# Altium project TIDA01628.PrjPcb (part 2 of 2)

## Sheet TIDA01628_Signal.SchDoc
size 431 x 279 mm; Date: Not shown in title block; ApprovedBy: Not shown in title block; CheckedBy: Not shown in title block; Author: Not shown in title block; CompanyName: Not shown in title block; Engineer: Not shown in title block; Organization: Not shown in title block; Address1: Not shown in title block; Address2: Not shown in title block; Address3: Not shown in title block; Address4: Not shown in title block; DocumentNumber: 1; Revision: Use project parameter SCH_Rev; SheetNumber: 4; SheetTotal: 5; PageSetup: Record=PageOptions¦CenterHorizontal=True¦CenterVertical=True¦PrintScale=1.00¦XCorrection=1.00¦YCorrection=1.00¦PrintKind=0¦BorderSize=5000000¦LeftOffset=0¦BottomOffset=0¦Orientation=2¦PaperLength=1000¦PaperWidth=1000¦Scale=100¦PaperSource=15¦PrintQuality=600¦MediaType=1¦DitherType=10¦PaperKind=Letter¦PrintScaleMode=1
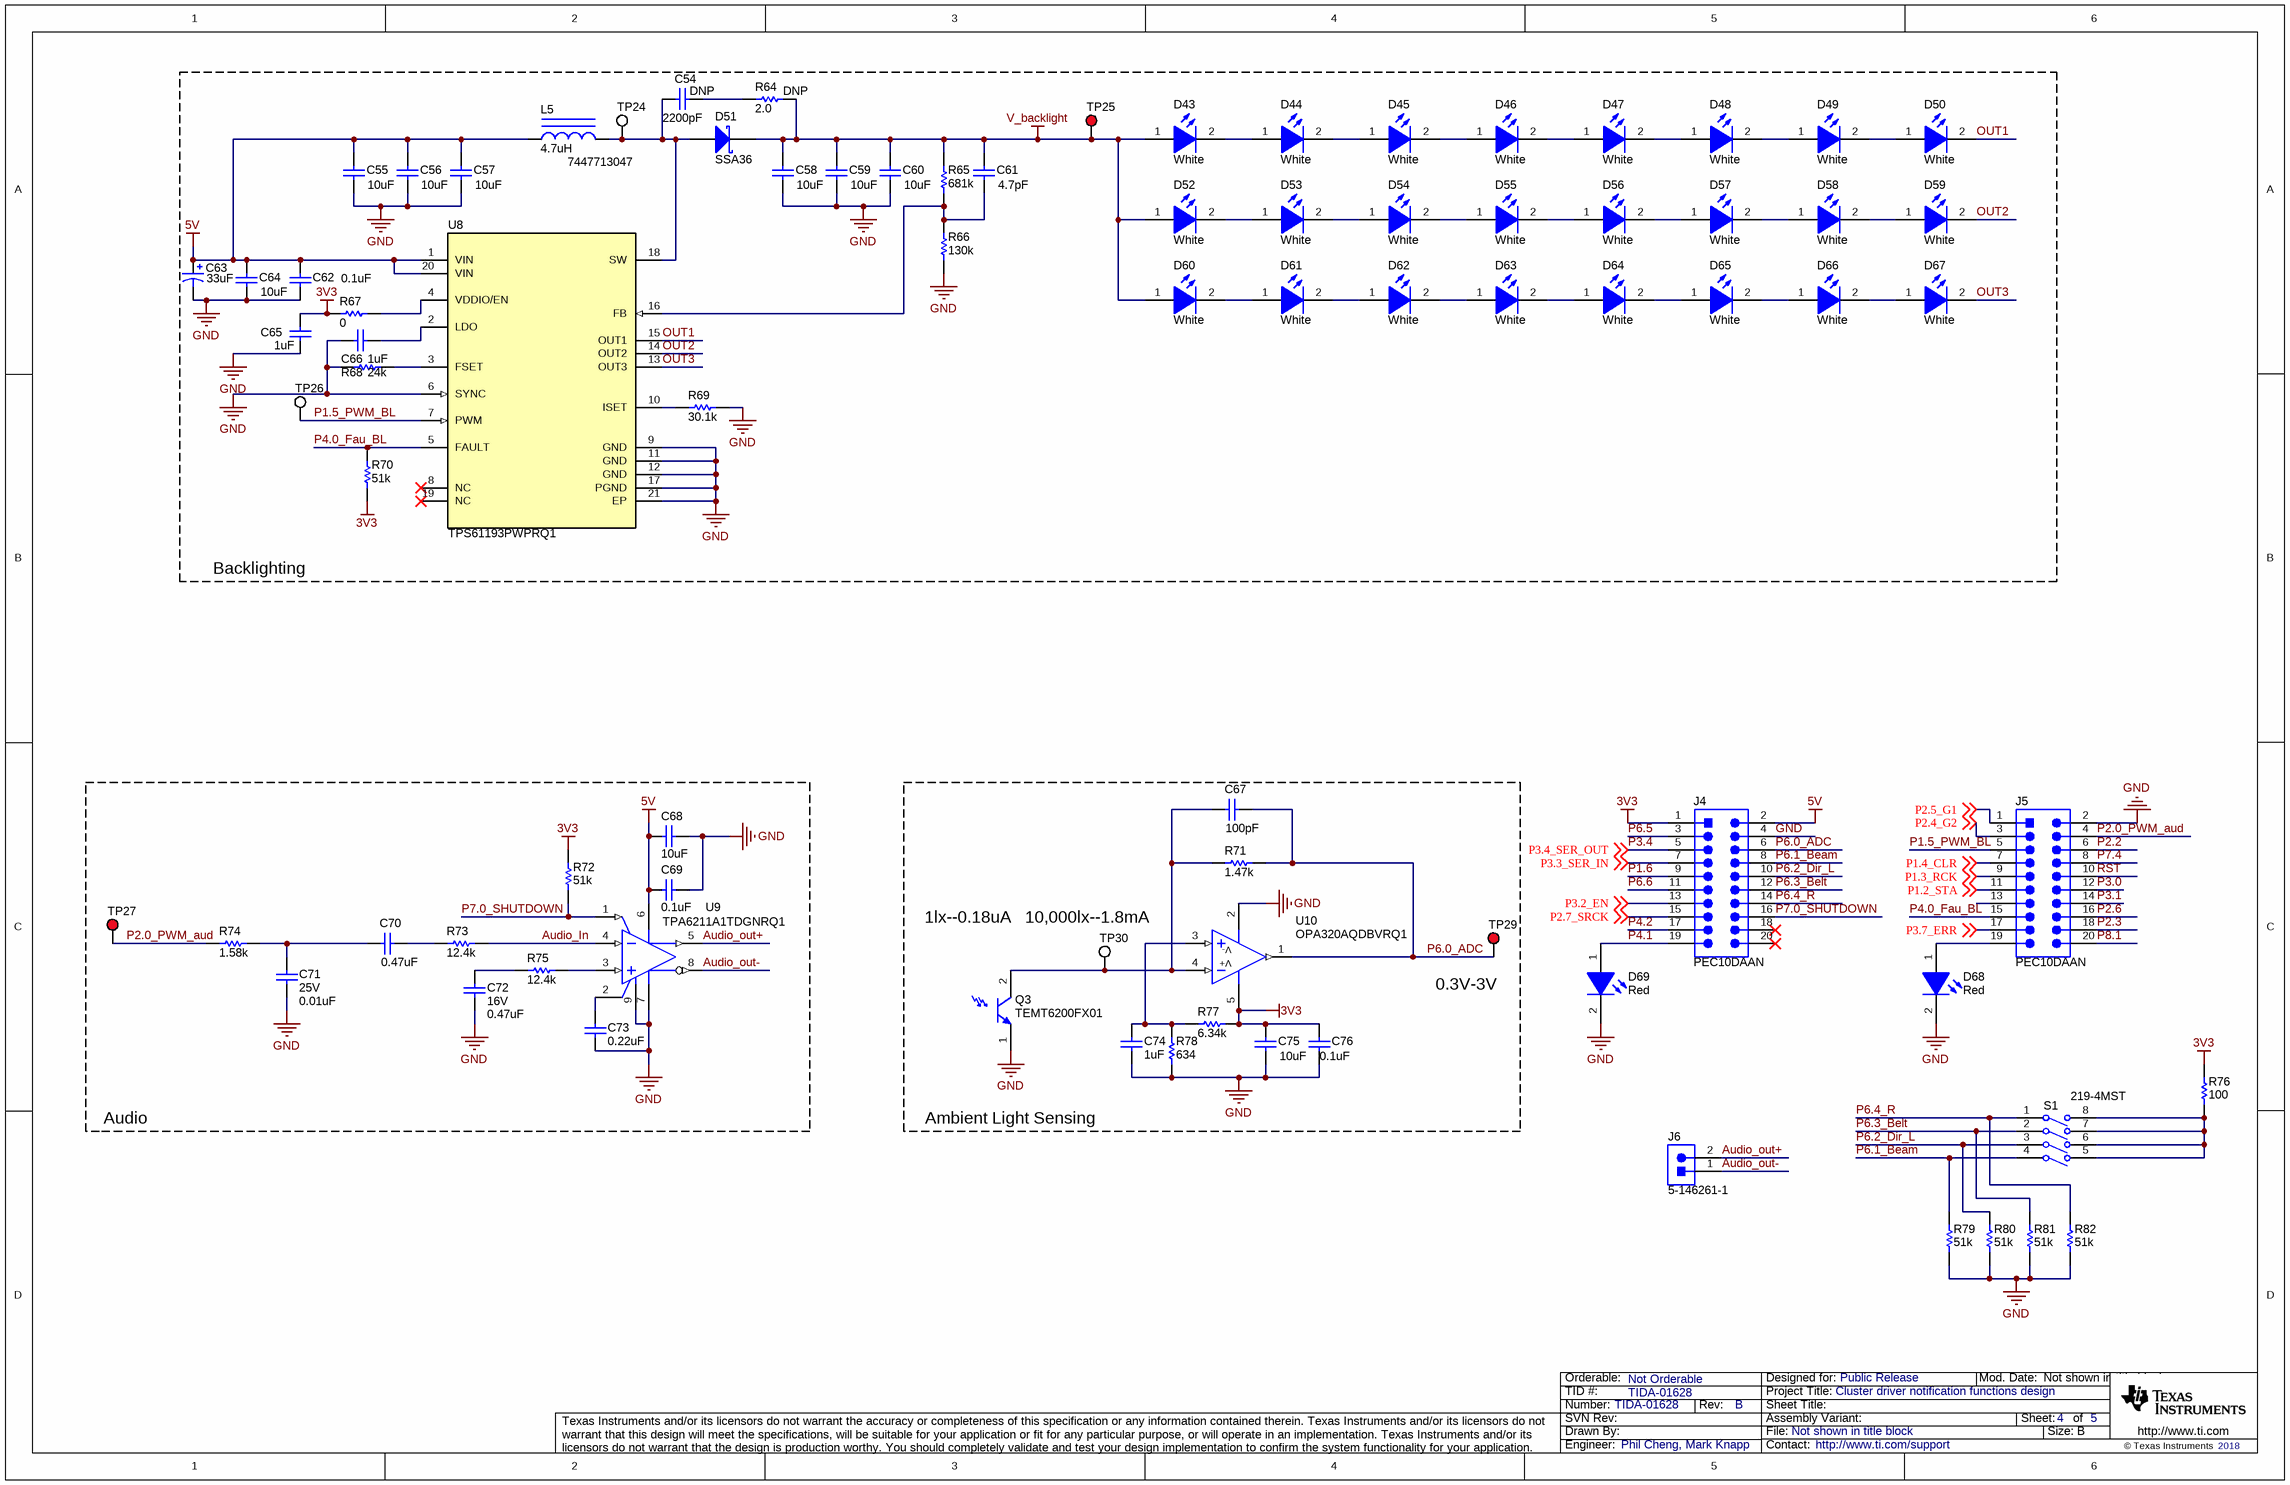
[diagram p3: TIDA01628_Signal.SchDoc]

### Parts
C54  DNP  ValueDisplayed: 2200pF  [0402]
C55  ValueDisplayed: 10uF  [1210_280]  (hidden comment: UMK325AB7106KMHT)
C56  ValueDisplayed: 10uF  [1210_280]  (hidden comment: UMK325AB7106KMHT)
C57  ValueDisplayed: 10uF  [1210_280]  (hidden comment: UMK325AB7106KMHT)
C58  ValueDisplayed: 10uF  [1210_280]  (hidden comment: UMK325AB7106KMHT)
C59  ValueDisplayed: 10uF  [1210_280]  (hidden comment: UMK325AB7106KMHT)
C60  ValueDisplayed: 10uF  [1210_280]  (hidden comment: UMK325AB7106KMHT)
C61  ValueDisplayed: 4.7pF  [0603]  (hidden comment: 06035A4R7CAT2A)
C62  ValueDisplayed: 0.1uF  [0402]  (hidden comment: GCM155R71H104KE02D)
C63  ValueDisplayed: 33uF  [SM_RADIAL_D]  (hidden comment: EEE-FK1V330P)
C64  ValueDisplayed: 10uF  [1210_280]  (hidden comment: UMK325AB7106KMHT)
C65  ValueDisplayed: 1uF  [0603]  (hidden comment: GCM188R71C105KA64D)
C66  ValueDisplayed: 1uF  [0603]  (hidden comment: GCM188R71C105KA64D)
C67  ValueDisplayed: 100pF  [0603]  (hidden comment: C1608C0G1H101J080AE)
C68  ValueDisplayed: 10uF  [1210_280]  (hidden comment: UMK325AB7106KMHT)
C69  ValueDisplayed: 0.1uF  [0402]  (hidden comment: GCM155R71H104KE02D)
C70  ValueDisplayed: 0.47uF  [0603]  (hidden comment: GCM188R71C474KA55D)
C71  VDC_V: 25V  ValueDisplayed: 0.01uF  [0402]  (hidden comment: GCM155R71E103KA37D)
C72  VDC_V: 16V  ValueDisplayed: 0.47uF  [0603]  (hidden comment: GCM188R71C474KA55D)
C73  ValueDisplayed: 0.22uF  [0603]  (hidden comment: CGA3E3X7R1H224K080AB)
C74  ValueDisplayed: 1uF  [0603]  (hidden comment: GCM188R71C105KA64D)
C75  ValueDisplayed: 10uF  [1210_280]  (hidden comment: UMK325AB7106KMHT)
C76  ValueDisplayed: 0.1uF  [0402]  (hidden comment: GCM155R71H104KE02D)
D43  value White  [KW_DPLS32_EC_White]  (hidden comment: KW DPLS32.EC-6H6J-4F8G-1)
D44  value White  [KW_DPLS32_EC_White]  (hidden comment: KW DPLS32.EC-6H6J-4F8G-1)
D45  value White  [KW_DPLS32_EC_White]  (hidden comment: KW DPLS32.EC-6H6J-4F8G-1)
D46  value White  [KW_DPLS32_EC_White]  (hidden comment: KW DPLS32.EC-6H6J-4F8G-1)
D47  value White  [KW_DPLS32_EC_White]  (hidden comment: KW DPLS32.EC-6H6J-4F8G-1)
D48  value White  [KW_DPLS32_EC_White]  (hidden comment: KW DPLS32.EC-6H6J-4F8G-1)
D49  value White  [KW_DPLS32_EC_White]  (hidden comment: KW DPLS32.EC-6H6J-4F8G-1)
D50  value White  [KW_DPLS32_EC_White]  (hidden comment: KW DPLS32.EC-6H6J-4F8G-1)
D51  SSA36  [SMA]
D52  value White  [KW_DPLS32_EC_White]  (hidden comment: KW DPLS32.EC-6H6J-4F8G-1)
D53  value White  [KW_DPLS32_EC_White]  (hidden comment: KW DPLS32.EC-6H6J-4F8G-1)
D54  value White  [KW_DPLS32_EC_White]  (hidden comment: KW DPLS32.EC-6H6J-4F8G-1)
D55  value White  [KW_DPLS32_EC_White]  (hidden comment: KW DPLS32.EC-6H6J-4F8G-1)
D56  value White  [KW_DPLS32_EC_White]  (hidden comment: KW DPLS32.EC-6H6J-4F8G-1)
D57  value White  [KW_DPLS32_EC_White]  (hidden comment: KW DPLS32.EC-6H6J-4F8G-1)
D58  value White  [KW_DPLS32_EC_White]  (hidden comment: KW DPLS32.EC-6H6J-4F8G-1)
D59  value White  [KW_DPLS32_EC_White]  (hidden comment: KW DPLS32.EC-6H6J-4F8G-1)
D60  value White  [KW_DPLS32_EC_White]  (hidden comment: KW DPLS32.EC-6H6J-4F8G-1)
D61  value White  [KW_DPLS32_EC_White]  (hidden comment: KW DPLS32.EC-6H6J-4F8G-1)
D62  value White  [KW_DPLS32_EC_White]  (hidden comment: KW DPLS32.EC-6H6J-4F8G-1)
D63  value White  [KW_DPLS32_EC_White]  (hidden comment: KW DPLS32.EC-6H6J-4F8G-1)
D64  value White  [KW_DPLS32_EC_White]  (hidden comment: KW DPLS32.EC-6H6J-4F8G-1)
D65  value White  [KW_DPLS32_EC_White]  (hidden comment: KW DPLS32.EC-6H6J-4F8G-1)
D66  value White  [KW_DPLS32_EC_White]  (hidden comment: KW DPLS32.EC-6H6J-4F8G-1)
D67  value White  [KW_DPLS32_EC_White]  (hidden comment: KW DPLS32.EC-6H6J-4F8G-1)
D68  value Red  [LED_LTST-C170_Red]  (hidden comment: LTST-C170KRKT)
D69  value Red  [LED_LTST-C170_Red]  (hidden comment: LTST-C170KRKT)
J4  PEC10DAAN  [SULLINS_PEC10DAAN]
J5  PEC10DAAN  [SULLINS_PEC10DAAN]
J6  5-146261-1  [CONN_5-146261-1]
L5  7447713047  ValueDisplayed: 4.7uH  [WE-PD_1030]
Q3  TEMT6200FX01  [VISHAY_TEMT6200FX01]
R64  DNP  ValueDisplayed: 2.0  [2010]
R65  ValueDisplayed: 681k  [0402]  (hidden comment: CRCW0402681KFKED)
R66  ValueDisplayed: 130k  [0402]  (hidden comment: CRCW0402130KFKED)
R67  ValueDisplayed: 0  [0402]  (hidden comment: CRCW04020000Z0ED)
R68  ValueDisplayed: 24k  [0402]  (hidden comment: CRCW040224K0JNED)
R69  ValueDisplayed: 30.1k  [0603]  (hidden comment: CRCW060330K1FKEA)
R70  ValueDisplayed: 51k  [0402]  (hidden comment: CRCW040251K0JNED)
R71  ValueDisplayed: 1.47k  [0603]  (hidden comment: CRCW06031K47FKEA)
R72  ValueDisplayed: 51k  [0402]  (hidden comment: CRCW040251K0JNED)
R73  ValueDisplayed: 12.4k  [0402]  (hidden comment: CRCW040212K4FKED)
R74  ValueDisplayed: 1.58k  [0402]  (hidden comment: CRCW04021K58FKED)
R75  ValueDisplayed: 12.4k  [0402]  (hidden comment: CRCW040212K4FKED)
R76  ValueDisplayed: 100  [0603]  (hidden comment: ERJ-3EKF1000V)
R77  ValueDisplayed: 6.34k  [0603]  (hidden comment: CRCW06036K34FKEA)
R78  ValueDisplayed: 634  [0603]  (hidden comment: CRCW0603634RFKEA)
R79  ValueDisplayed: 51k  [0402]  (hidden comment: CRCW040251K0JNED)
R80  ValueDisplayed: 51k  [0402]  (hidden comment: CRCW040251K0JNED)
R81  ValueDisplayed: 51k  [0402]  (hidden comment: CRCW040251K0JNED)
R82  ValueDisplayed: 51k  [0402]  (hidden comment: CRCW040251K0JNED)
S1  219-4MST  [SW_219-4MST]
TP24  5002  [Keystone5002]  (value not drawn)
TP25  5000  [Keystone5000]  (value not drawn)
TP26  5002  [Keystone5002]  (value not drawn)
TP27  5000  [Keystone5000]  (value not drawn)
TP29  5000  [Keystone5000]  (value not drawn)
TP30  5002  [Keystone5002]  (value not drawn)
U8  TPS61193PWPRQ1  [PWP0020D_M]
U9  TPA6211A1TDGNRQ1  [DGN0008D_L]
U10  OPA320AQDBVRQ1  [DBV0005A_N]

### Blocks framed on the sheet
Backlighting: C54-C66 D43-D67 L5 R64-R70 TP24-TP26 U8
Audio: C68-C73 R72-R75 TP27 U9

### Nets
3V3: C65.1 C75.1 C76.1 J4.1 R67.2 R70.1 R72.2 R76.2 R77.2 U10.5(V+)
5V: C55.1 C56.1 C57.1 C62.1 C63.1(+) C64.1 C68.1 C69.1 J4.2 L5.1 U8.1(VIN) U8.20(VIN) U9.6(VDD)
GND: C55.2 C56.2 C57.2 C58.2 C59.2 C60.2 C62.2 C63.2(-) C64.2 C65.2 C66.2 C68.2 C69.2 C71.2 C72.2 C73.2 C74.2 C75.2 C76.2 D68.2(K) D69.2(K) J4.4 J5.2 Q3.1(E) R66.1 R68.1 R69.2 R78.1 R79.1 R80.1 R81.1 R82.1 U8.6(SYNC) U8.9(GND) U8.11(GND) U8.12(GND) U8.17(PGND) U8.21(EP) U9.7(GND) U9.9(EP) U10.2(V-)
V_backlight: C58.1 C59.1 C60.1 C61.1 D43.1(A) D51.1(K) D52.1(A) D60.1(A) R64.2 R65.2 TP25.1
Audio_In: R73.1 U9.4(IN-)
Audio_out+: J6.2 U9.5(VO+)
Audio_out-: J6.1 U9.8(VO-)
OUT1: D50.2(K) U8.15(OUT1)
OUT2: D59.2(K) U8.14(OUT2)
OUT3: D67.2(K) U8.13(OUT3)
P1.2_STA: J5.11 ; off-sheet P1.2_STA
P1.3_RCK: J5.9 ; off-sheet P1.3_RCK
P1.4_CLR: J5.7 ; off-sheet P1.4_CLR
P1.5_PWM_BL: J5.5 TP26.1 U8.7(PWM)
P1.6: J4.9
P2.0_PWM_aud: J5.4 R74.1 TP27.1
P2.2: J5.6
P2.3: J5.18
P2.4_G2: J5.3 ; off-sheet P2.4_G2
P2.5_G1: J5.1 ; off-sheet P2.5_G1
P2.6: J5.16
P2.7_SRCK: J4.15 ; off-sheet P2.7_SRCK
P3.0: J5.12
P3.1: J5.14
P3.2_EN: J4.13 ; off-sheet P3.2_EN
P3.3_SER_IN: J4.7 ; off-sheet P3.3_SER_IN
P3.4: J4.5 ; off-sheet P3.4_SER_OUT  [also labelled P3.4_SER_OUT]
P3.7_ERR: J5.17 ; off-sheet P3.7_ERR
P4.0_Fau_BL: J5.15 R70.2 U8.5(FAULT)
P4.1: D69.1(A) J4.19
P4.2: J4.17
P6.0_ADC: C67.1 J4.6 R71.2 TP29.1 U10.1(OUT)
P6.1_Beam: J4.8 R79.2 S1.4(A4)
P6.2_Dir_L: J4.10 R80.2 S1.3(A3)
P6.3_Belt: J4.12 R81.2 S1.2(A2)
P6.4_R: J4.14 R82.2 S1.1(A1)
P6.5: J4.3
P6.6: J4.11
P7.0_SHUTDOWN: J4.16 R72.1 U9.1(~{SHUTDOWN})
P7.4: J5.8
P8.1: J5.20
RST: J5.10
NetC54_1: C54.1 R64.1
NetC54_2: C54.2 D51.2(A) L5.2 TP24.1 U8.18(SW)
NetC61_2: C61.2 R65.1 R66.2 U8.16(FB)
NetC66_1: C66.1 U8.2(LDO)
NetC67_2: C67.2 Q3.2(C) R71.1 TP30.1 U10.4(IN-)
NetC70_1: C70.1 R73.2
NetC70_2: C70.2 C71.1 R74.2
NetC72_1: C72.1 R75.1
NetC73_1: C73.1 U9.2(BYPASS)
NetC74_1: C74.1 R77.1 R78.2 U10.3(IN+)
NetD43_2: D43.2(K) D44.1(A)
NetD44_2: D44.2(K) D45.1(A)
NetD45_2: D45.2(K) D46.1(A)
NetD46_2: D46.2(K) D47.1(A)
NetD47_2: D47.2(K) D48.1(A)
NetD48_2: D48.2(K) D49.1(A)
NetD49_2: D49.2(K) D50.1(A)
NetD52_2: D52.2(K) D53.1(A)
NetD53_2: D53.2(K) D54.1(A)
NetD54_2: D54.2(K) D55.1(A)
NetD55_2: D55.2(K) D56.1(A)
NetD56_2: D56.2(K) D57.1(A)
NetD57_2: D57.2(K) D58.1(A)
NetD58_2: D58.2(K) D59.1(A)
NetD60_2: D60.2(K) D61.1(A)
NetD61_2: D61.2(K) D62.1(A)
NetD62_2: D62.2(K) D63.1(A)
NetD63_2: D63.2(K) D64.1(A)
NetD64_2: D64.2(K) D65.1(A)
NetD65_2: D65.2(K) D66.1(A)
NetD66_2: D66.2(K) D67.1(A)
NetD68_1: D68.1(A) J5.19
NetR67_1: R67.1 U8.4(VDDIO/EN)
NetR68_2: R68.2 U8.3(FSET)
NetR69_1: R69.1 U8.10(ISET)
NetR75_2: R75.2 U9.3(IN+)
NetR76_1: R76.1 S1.5(B4) S1.6(B3) S1.7(B2) S1.8(B1)

Not connected (* = marked no-connect by the designer): J4 18* 20*; J5 13; U8 8(NC)* 19(NC)*

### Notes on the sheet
- (near TP30) 1lx--0.18uA   10,000lx--1.8mA
- (near TP29) 0.3V-3V
- Ambient Light Sensing

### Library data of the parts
C54 = CMP-0006357-2: CAP, CERM, 2200 pF, 50 V, +/- 10%, X7R, AEC-Q200 Grade 1, 0402; Manufacturer: MuRata; PartNumber: GCM155R71H222KA37D; TaMin_C: -55°C; Polarized: N; SizeAreaWB_mm2: 3; Value1: Unknown; U/M: EA; Value: 2200pF; TaMax_C: 125°C; SizeZ_mm: 0.6; SizeX_mm: 1; SizeY_mm: 0.5; Value2: 50V; CompType: Capacitor; AEC Qualified: Y; Cap_F: 2.2nF; AEC Category: Q200
C55-C60 C64 C68 C75 = CMP-0009258-2: CAP, CERM, 10 uF, 50 V, +/- 10%, X7R, AEC-Q200 Grade 1, 1210; Manufacturer: Taiyo Yuden; TaMin_C: -55°C; Polarized: N; SizeAreaWB_mm2: 14.7; Value1: Unknown; U/M: EA; Value: 10uF; TaMax_C: 125°C; SizeZ_mm: 2.8; SizeX_mm: 3.2; SizeY_mm: 2.5; Cap_Case: 1210; Value2: 50V; SizeArea_mm2: 8; CompType: Capacitor; AEC Qualified: Y; Cap_F: 10µF; AEC Grade: 1; AEC Category: Q200
C61 = CMP-0006791-4: CAP, CERM, 4.7 pF, 50 V, +/- 5%, C0G/NP0, 0603; Manufacturer: AVX; TaMin_C: -55°C; ESR_ohm: 6.33d; Polarized: N; SizeAreaWB_mm2: 4.68; Value1: 0.633 ohm; U/M: EA; Value: 4.7pF; TaMax_C: 125°C; SizeZ_mm: 1; SizeX_mm: 1.6; SizeY_mm: 0.8; Value2: 50V; SizeArea_mm2: 1.28; CompType: Capacitor; AEC Category: Q200
C62 C69 C76 = CMP-0006356-2: CAP, CERM, 0.1 uF, 50 V, +/- 10%, X7R, AEC-Q200 Grade 1, 0402; Manufacturer: MuRata; TaMin_C: -55°C; Polarized: N; SizeAreaWB_mm2: 3; Value1: Unknown; U/M: EA; Value: 0.1uF; TaMax_C: 125°C; SizeZ_mm: 0.6; SizeX_mm: 1; SizeY_mm: 0.5; Value2: 50V; CompType: Capacitor; AEC Qualified: Y; Cap_F: 100nF; AEC Category: Q200
C63 = CMP-0010728-1: CAP, AL, 33 uF, 35 V, +/- 20%, 0.36 ohm, AEC-Q200 Grade 2, SMD; Manufacturer: Panasonic; TaMin_C: -55°C; ESR_ohm: 3.6d; Polarized: Y; SizeAreaWB_mm2: 84.28; U/M: EA; Value: 33uF; TaMax_C: 105°C; SizeZ_mm: 5.4; SizeX_mm: 7.8; SizeY_mm: 6.6; Cap_Case: D; Value2: 35V; SizeArea_mm2: 51.48; CompType: Capacitor; Cap_F: 33µF; IRMS_A: 2.4dA; AEC Grade: 2; AEC Category: Q200
C65 C66 C74 = CMP-0007136-5: CAP, CERM, 1 uF, 16 V, +/- 10%, X7R, AEC-Q200 Grade 1, 0603; Manufacturer: MuRata; TaMin_C: -55°C; Polarized: N; SizeAreaWB_mm2: 4.68; Value1: Unknown; U/M: EA; Value: 1uF; TaMax_C: 125°C; SizeZ_mm: 1; SizeX_mm: 1.6; SizeY_mm: 0.8; Value2: 16V; SizeArea_mm2: 1.28; CompType: Capacitor; AEC Qualified: Y; Cap_F: 1µF; AEC Category: Q200
C67 = CMP-0006989-4: CAP, CERM, 100 pF, 50 V, +/- 5%, C0G/NP0, 0603; Manufacturer: TDK; TaMin_C: -55°C; Polarized: N; SizeAreaWB_mm2: 4.68; Value1: Unknown; U/M: EA; Value: 100pF; TaMax_C: 125°C; SizeZ_mm: 1; SizeX_mm: 1.6; SizeY_mm: 0.8; Value2: 50V; SizeArea_mm2: 1.28; CompType: Capacitor; AEC Category: Q200
C70 = CMP-0007138-4: CAP, CERM, 0.47 uF, 16 V, +/- 10%, X7R, AEC-Q200 Grade 1, 0603; Manufacturer: MuRata; TaMin_C: -55°C; Polarized: N; SizeAreaWB_mm2: 4.68; Value1: Unknown; U/M: EA; Value: 0.47uF; TaMax_C: 125°C; SizeZ_mm: 1; SizeX_mm: 1.6; SizeY_mm: 0.8; Value2: 16V; SizeArea_mm2: 1.28; CompType: Capacitor; AEC Qualified: Y; Cap_F: 470nF; AEC Category: Q200
C71 = CMP-0006352-2: CAP, CERM, 0.01 uF, 25 V, +/- 10%, X7R, 0402; Manufacturer: MuRata; TaMin_C: -55°C; Polarized: N; SizeAreaWB_mm2: 3; Value1: Unknown; U/M: EA; Value: 0.01uF; TaMax_C: 125°C; SizeZ_mm: 0.6; SizeX_mm: 1; SizeY_mm: 0.5; Cap_F: 10nF; AEC Category: Q200
C72 = CMP-0007138-4: CAP, CERM, 0.47 uF, 16 V, +/- 10%, X7R, AEC-Q200 Grade 1, 0603; Manufacturer: MuRata; TaMin_C: -55°C; Polarized: N; SizeAreaWB_mm2: 4.68; Value1: Unknown; U/M: EA; Value: 0.47uF; TaMax_C: 125°C; SizeZ_mm: 1; SizeX_mm: 1.6; SizeY_mm: 0.8; SizeArea_mm2: 1.28; AEC Qualified: Y; Cap_F: 470nF; AEC Category: Q200
C73 = CMP-0007094-5: CAP, CERM, 0.22 uF, 50 V, +/- 10%, X7R, AEC-Q200 Grade 1, 0603; Manufacturer: TDK; TaMin_C: -55°C; ESR_ohm: 0.021699; Polarized: N; SizeAreaWB_mm2: 4.68; Value1: 0.021699 ohm; U/M: EA; Value: 0.22uF; TaMax_C: 125°C; SizeZ_mm: 1; SizeX_mm: 1.6; SizeY_mm: 0.8; Value2: 50V; SizeArea_mm2: 1.28; CompType: Capacitor; AEC Qualified: Y; Cap_F: 220nF; IRMS_A: 1.12496A; AEC Category: Q200
D43-D50 D52-D67 = KW DPLS32.EC-6H6J-4F8G-1: LED, White, SMD; Manufacturer: OSRAM; Type: InGaN; Vf_V: 3.15; Value2: 3.15V; Io_A: 0.12; Tjmax_C: 125; Value1: W; Angle: 120; SizeAreaWB_mm2: 12; SizeArea_mm2: 5.6; SizeX_mm: 4; SizeY_mm: 1.4; SizeZ_mm: 0.75; U/M: EA
D51 = CMP-0028810-1: Diode, Schottky, 60 V, 3 A, AEC-Q101, SMA; Manufacturer: Fairchild Semiconductor; Io_A: 3A; Green_Lifecycle: Not Set; SizeAreaWB_mm2: 37.3428; Vr_V: 60V; Green_REACh: Incomplete; TJmax_C: 150°C; U/M: EA; Value: 60V; SizeZ_mm: 2.87; SizeX_mm: 5.59; SizeY_mm: 2.92; Vf_V: 7.5dV; Value2: 0.75V; SizeArea_mm2: 16.3228; AEC Qualified: Y; AEC Category: Q101
D68 D69 = LTST-C170KRKT: LED, Red, SMD; Manufacturer: Lite-On; Type: AlInGaP; Vf_V: 2; Value2: 2V; Io_A: 0.02; Value1: W; SizeAreaWB_mm2: 6.75; SizeArea_mm2: 2.5; SizeY_mm: 1.25; SizeZ_mm: 1.2; U/M: EA; Green_Lifecycle: Active; Green_REACh: Passed
J4 J5 = CMP-0054623-1: Header, 2.54mm, 10x2, Tin, TH; Manufacturer: Sullins Connector Solutions; CNHeader: TRUE; Current_A: 3A; Green_Lifecycle: Not Set; Shrouded: N; Gender: Male; Green_REACh: Incomplete; Row_Count: 2; RowSpacing_mm: 2.54; CT: FALSE; Cert_UL: Y
J6 = CMP-0054947-1: Header, 100mil, 2x1, Gold, TH; Manufacturer: TE Connectivity; CT: FALSE; Green_REACh: Passed; CNHeader: TRUE; Green_Lifecycle: Active
L5 = CMP-0064217-1: Inductor, Shielded Drum Core, Ferrite, 4.7 uH, 4 A, 0.026 ohm, SMD; Manufacturer: Wurth Elektronik; Isat: 6A @ 10% inductance drop; Irms: 4A @ 40C rise; Green_Lifecycle: Active; SizeAreaWB_mm2: 144; DCR_ohm: 0.026; Green_REACh: Passed; Value: 4.7uH; Imax_A: 4A; SizeZ_mm: 3; SizeX_mm: 10; SizeArea_mm2: 100; Ind_H: 4.7µH; AEC Category: Q200
Q3 = CMP-0002104-2: Ambient Light Sensor in 0805 Package; Manufacturer: Vishay-Semiconductor; Value: 550nm
R64 = CMP-0016110-3: RES, 2.0, 5%, 0.75 W, AEC-Q200 Grade 0, 2010; Manufacturer: Vishay-Dale; PartNumber: CRCW20102R00JNEF; Power_W: 750mW; TempCo: 200 ppm/C; Value_Code: 2R00; Value: 2.0; EIA_Code: E24; Res_ohm: 2; SizeX_mm: 5; SizeY_mm: 2.5; SizeZ_mm: 1.66; Value2: 0.75W; SizeArea_mm2: 12.5; CompType: Resistor; AEC Qualified: Y; VDC_V: 400V; AEC Grade: 0; AEC Category: Q200
R65 = CMP-0026504-2: RES, 681 k, 1%, 0.063 W, AEC-Q200 Grade 0, 0402; Manufacturer: Vishay-Dale; Power_W: 63mW; TempCo: 100 ppm/C; Value: 681k; EIA_Code: E96; SizeX_mm: 1; SizeY_mm: 0.5; SizeZ_mm: 0.6; Value2: 0.063W; AEC Qualified: Y; VDC_V: 50V; AEC Category: Q200; AEC Grade: 0
R66 = CMP-0025997-3: RES, 130 k, 1%, 0.063 W, AEC-Q200 Grade 0, 0402; Manufacturer: Vishay-Dale; Power_W: 63mW; TempCo: 100 ppm/C; Value: 130k; EIA_Code: E96; SizeX_mm: 1; SizeY_mm: 0.5; SizeZ_mm: 0.6; Value2: 0.063W; AEC Qualified: Y; VDC_V: 50V; AEC Category: Q200; AEC Grade: 0
R67 = CMP-0026822-3: RES, 0, 5%, 0.063 W, AEC-Q200 Grade 0, 0402; Manufacturer: Vishay-Dale; Power_W: 63mW; TempCo: 200 ppm/C; Value_Code: 0000; Value: 0; EIA_Code: E24; SizeX_mm: 1; SizeY_mm: 0.5; SizeZ_mm: 0.6; Value2: 0.063W; AEC Qualified: Y; VDC_V: 50V; AEC Category: Q200
R68 = CMP-0026883-3: RES, 24 k, 5%, 0.063 W, AEC-Q200 Grade 0, 0402; Manufacturer: Vishay-Dale; Power_W: 63mW; TempCo: 200 ppm/C; Value_Code: 24k0; Value: 24k; EIA_Code: E24; SizeX_mm: 1; SizeY_mm: 0.5; SizeZ_mm: 0.6; Value2: 0.063W; AEC Qualified: Y; VDC_V: 50V; AEC Category: Q200; AEC Grade: 0
R69 = CMP-0022324-4: RES, 30.1 k, 1%, 0.1 W, AEC-Q200 Grade 0, 0603; Manufacturer: Vishay-Dale; Power_W: 100mW; TempCo: 100 ppm/C; Value_Code: 30k1; Value: 30.1k; EIA_Code: E96; SizeX_mm: 1.6; SizeY_mm: 0.8; SizeZ_mm: 1; Value2: 0.1W; SizeArea_mm2: 1.28; CompType: Resistor; AEC Qualified: Y; VDC_V: 75V; AEC Category: Q200; AEC Grade: 0
R70 R72 R79-R82 = CMP-0026945-3: RES, 51 k, 5%, 0.063 W, AEC-Q200 Grade 0, 0402; Manufacturer: Vishay-Dale; Power_W: 63mW; TempCo: 200 ppm/C; Value_Code: 51k0; Value: 51k; EIA_Code: E24; SizeX_mm: 1; SizeY_mm: 0.5; SizeZ_mm: 0.6; Value2: 0.063W; AEC Qualified: Y; VDC_V: 50V; AEC Category: Q200; AEC Grade: 0
R71 = CMP-0022125-4: RES, 1.47 k, 1%, 0.1 W, AEC-Q200 Grade 0, 0603; Manufacturer: Vishay-Dale; Power_W: 100mW; TempCo: 100 ppm/C; Value_Code: 1k47; Value: 1.47k; EIA_Code: E96; SizeX_mm: 1.6; SizeY_mm: 0.8; SizeZ_mm: 1; Value2: 0.1W; SizeArea_mm2: 1.28; AEC Qualified: Y; VDC_V: 75V; AEC Category: Q200; AEC Grade: 0
R73 = CMP-0025992-3: RES, 12.4 k, 1%, 0.063 W, AEC-Q200 Grade 0, 0402; Manufacturer: Vishay-Dale; Power_W: 63mW; TempCo: 100 ppm/C; Value_Code: 12k4; Value: 12.4k; EIA_Code: E96; SizeX_mm: 1; SizeY_mm: 0.5; SizeZ_mm: 0.6; Value2: 0.063W; CompType: Resistor; AEC Qualified: Y; VDC_V: 50V; AEC Category: Q200; AEC Grade: 0
R74 = CMP-0026090-3: RES, 1.58 k, 1%, 0.063 W, AEC-Q200 Grade 0, 0402; Manufacturer: Vishay-Dale; Power_W: 63mW; TempCo: 100 ppm/C; Value_Code: 1k58; Value: 1.58k; EIA_Code: E96; SizeX_mm: 1; SizeY_mm: 0.5; SizeZ_mm: 0.6; Value2: 0.063W; AEC Qualified: Y; VDC_V: 50V; AEC Category: Q200; AEC Grade: 0
R75 = CMP-0025992-3: RES, 12.4 k, 1%, 0.063 W, AEC-Q200 Grade 0, 0402; Manufacturer: Vishay-Dale; Power_W: 63mW; TempCo: 100 ppm/C; Value_Code: 12k4; Value: 12.4k; EIA_Code: E96; SizeX_mm: 1; SizeY_mm: 0.5; SizeZ_mm: 0.6; Value2: 0.063W; AEC Qualified: Y; VDC_V: 50V; AEC Category: Q200; AEC Grade: 0
R76 = CMP-0022679-3: RES, 100, 1%, 0.1 W, AEC-Q200 Grade 0, 0603; Manufacturer: Panasonic; Power_W: 100mW; TempCo: 100 ppm/C; Value_Code: 100R; U/M: EA; Value: 100; EIA_Code: E96; SizeX_mm: 1.6; SizeY_mm: 0.8; SizeZ_mm: 1; Value2: 0.1W; SizeArea_mm2: 1.28; AEC Qualified: Y; AEC Grade: 0; AEC Category: Q200
R77 = CMP-0022560-4: RES, 6.34 k, 1%, 0.1 W, AEC-Q200 Grade 0, 0603; Manufacturer: Vishay-Dale; Power_W: 100mW; TempCo: 100 ppm/C; Value_Code: 6k34; Value: 6.34k; EIA_Code: E96; SizeX_mm: 1.6; SizeY_mm: 0.8; SizeZ_mm: 1; Value2: 0.1W; SizeArea_mm2: 1.28; AEC Qualified: Y; VDC_V: 75V; AEC Category: Q200; AEC Grade: 0
R78 = CMP-0022539-5: RES, 634, 1%, 0.1 W, AEC-Q200 Grade 0, 0603; Manufacturer: Vishay-Dale; Power_W: 100mW; TempCo: 100 ppm/C; Value_Code: 634R; Value: 634; EIA_Code: E96; SizeX_mm: 1.6; SizeY_mm: 0.8; SizeZ_mm: 1; Value2: 0.1W; SizeArea_mm2: 1.28; CompType: Resistor; AEC Qualified: Y; VDC_V: 75V; AEC Category: Q200; AEC Grade: 0
S1 = CMP-0002291-1: Switch, SPST, Slide, Off-On, 4 Pos, 0.1A, 20V, SMD; Manufacturer: CTS Electrocomponents; CurrentRating_mA: 100A; PositionCount: 4; SizeX_mm: 9.91; SizeY_mm: 11.63; SizeZ_mm: 4.23; SizeArea_mm2: 115.2533; SizeAreaWB_mm2: 162.3333
TP24 TP26 TP30 = CMP-0055139-1: Test Point, Miniature, White, TH; Manufacturer: Keystone; CNHeader: FALSE; Green_Lifecycle: Active; Green_REACh: Passed; ContactFinish: Silver; CT: TRUE
TP25 TP27 TP29 = CMP-0055137-1: Test Point, Miniature, Red, TH; Manufacturer: Keystone; CNHeader: FALSE; Green_Lifecycle: Active; Green_REACh: Passed; ContactFinish: Silver; CT: TRUE
U8 = CMP-0073707-2: Low-EMI, High-Performance 3-Channel LED Driver for Automotive Lighting, PWP0020D (TSSOP-20); Alternate Manufacturer: Texas Instruments; Green_Lifecycle: Active; SizeAreaWB_mm2: 71.4; Green_REACh: Passed; U/M: EA; SizeZ_mm: 1.2; SizeX_mm: 6.4; SizeY_mm: 6.5; SizeArea_mm2: 41.6; CompType: IC
U9 = CMP-0043047-1: Automotive Catalog 3.1-W Mono, Fully Differential, Class-AB Audio Amplifier, -40 to 105 degC, 8-pin SOP (DGN8), Green (RoHS & no Sb/Br); Manufacturer: Texas Instruments; Output Power(W): 2.45; SubFamily: Dynamic Speaker; Supply Max(Max)(Volt): 5.5; PSRR(dB): -85; Supply Min(Min)(Volt): 2.5
U10 = CMP-0077859-1: Automotive Qualified Precision, Zero-Crossover, 20MHz, 0.9pA Ib, RRIO, CMOS Operational Amplifier, DBV0005A (SOT-23-5); Alternate PartNumber: OPA320AQDBVTQ1; Alternate Manufacturer: Texas Instruments; SizeAreaWB_mm2: 14.82; SizeZ_mm: 1.45; SizeX_mm: 2.8; SizeY_mm: 2.9; SizeArea_mm2: 8.12; CompType: IC; AEC Qualified: Y; AEC Category: Q200

## Sheet TIDA01628_Hardware.SchDoc
size 431 x 279 mm; Date: Not shown in title block; ApprovedBy: Not shown in title block; CheckedBy: Not shown in title block; Author: Not shown in title block; CompanyName: Not shown in title block; Engineer: Not shown in title block; Organization: Not shown in title block; Address1: Not shown in title block; Address2: Not shown in title block; Address3: Not shown in title block; Address4: Not shown in title block; DocumentNumber: 1; Revision: Use project parameter SCH_Rev; SheetNumber: 5; SheetTotal: 5; PageSetup: Record=PageOptions¦CenterHorizontal=True¦CenterVertical=True¦PrintScale=1.00¦XCorrection=1.00¦YCorrection=1.00¦PrintKind=0¦BorderSize=5000000¦LeftOffset=0¦BottomOffset=0¦Orientation=2¦PaperLength=1000¦PaperWidth=1000¦Scale=100¦PaperSource=15¦PrintQuality=600¦MediaType=1¦DitherType=10¦PaperKind=Letter¦PrintScaleMode=1
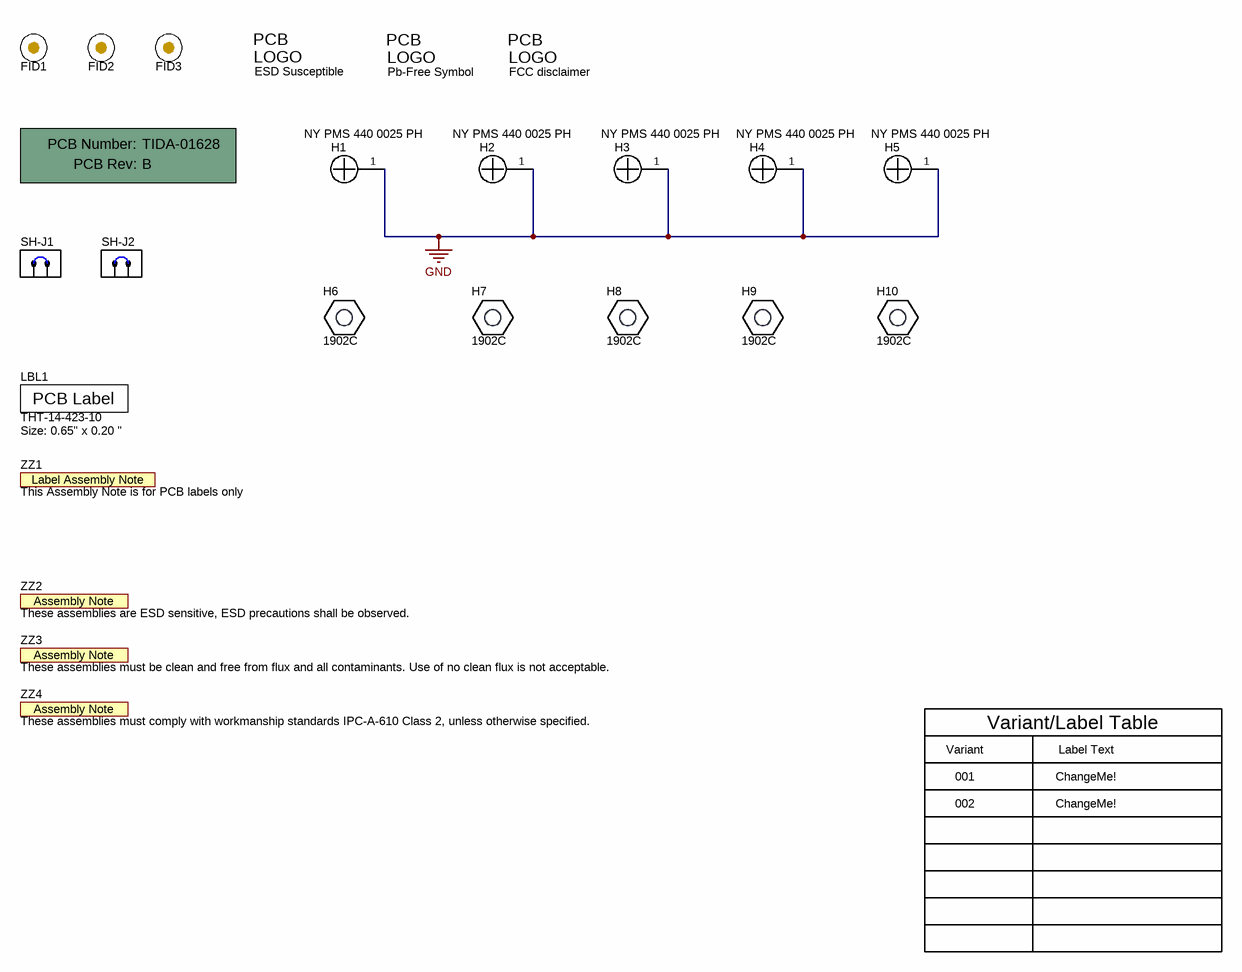
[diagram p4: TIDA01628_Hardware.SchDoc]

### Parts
!PCB1  Printed Circuit Board  (value not drawn)  (mechanical)
FID1  Fiducial  [Fiducial10-20]  (value not drawn)
FID2  Fiducial  [Fiducial10-20]  (value not drawn)
FID3  Fiducial  [Fiducial10-20]  (value not drawn)
H1  NY PMS 440 0025 PH  [NY PMS 440 0025 PH]
H2  NY PMS 440 0025 PH  [NY PMS 440 0025 PH]
H3  NY PMS 440 0025 PH  [NY PMS 440 0025 PH]
H4  NY PMS 440 0025 PH  [NY PMS 440 0025 PH]
H5  NY PMS 440 0025 PH  [NY PMS 440 0025 PH]
H6  1902C  [Keystone_1902C]
H7  1902C  [Keystone_1902C]
H8  1902C  [Keystone_1902C]
H9  1902C  [Keystone_1902C]
H10  1902C  [Keystone_1902C]
LBL1  THT-14-423-10  Note: Size: 0.65" x 0.20 "  [Label_650x200]
Logo1  ESD Susceptible  [ESD_Overlay_Large]  (no BOM)
Logo2  Pb-Free Symbol  [Pb-Free_Overlay_Small]  (no BOM)
Logo3  FCC disclaimer  [FCC_disclaimer]  (no BOM)
SH-J1  M7582-05  [Harwin_M7582-05]  (value not drawn)
SH-J2  M7582-05  [Harwin_M7582-05]  (value not drawn)
ZZ1  This Assembly Note is for PCB labels only  [AssemblyNoteLabel]  (no BOM)
ZZ2  These assemblies are ESD sensitive, ESD precautions shall be observed.  [AssemblyNote]  (no BOM)
ZZ3  These assemblies must be clean and free from flux and all contaminants. Use of no clean flux is not acceptable.  [AssemblyNote]  (no BOM)
ZZ4  These assemblies must comply with workmanship standards IPC-A-610 Class 2, unless otherwise specified.  [AssemblyNote]  (no BOM)

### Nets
GND: H1.1 H2.1 H3.1 H4.1 H5.1

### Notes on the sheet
- Variant
- Variant/Label Table
- Label Text
- 001
- 002
- ChangeMe!

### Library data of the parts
!PCB1 = CMP-0003618-2: Manufacturer: Any; PartNumber: TIDA-01628; CompType: PCB
FID1-FID3 = CMP-0077181-1: Fiducial mark.  There is nothing to buy or mount.
H1-H5 = CMP-0003617-1: Machine Screw, Round, #4-40 x 1/4, Nylon, Philips panhead; Manufacturer: B&F Fastener Supply; CompType: Hardware
H6-H10 = CMP-0003610-1: Standoff, Hex, 0.5"L #4-40 Nylon; Manufacturer: Keystone; CompType: Hardware
LBL1 = CMP-0003625-1: Thermal Transfer Printable Labels, 0.650" W x 0.200" H - 10,000 per roll; Manufacturer: Brady; CompType: Label
Logo1 = CMP-0074840-1: ESD Susceptible Symbol; Library Reference: Logo; SymbolCreator: a0412235; Lib Reference: ESD_Susceptible
Logo2 = CMP-0074839-1: SymbolCreator: a0412235; Library Reference: Logo
Logo3 = CMP-0074847-1: FCC_disclaimer; Library Reference: Logo
SH-J1 SH-J2 = CMP-0078738-1: Single Operation 2.54mm Pitch Open Top Jumper Socket; Manufacturer: Harwin; CompType: Shunt
ZZ1 = CMP-0003616-3
ZZ2 = CMP-0077236-1
ZZ3 = CMP-0077237-1
ZZ4 = CMP-0077238-1

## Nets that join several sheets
3V3: TIDA01628_Telltale (9 pins), TIDA01628_Power (12 pins), TIDA01628_Signal (10 pins)
5V: TIDA01628_Telltale (46 pins), TIDA01628_Power (8 pins), TIDA01628_Signal (13 pins)
GND: TIDA01628_Telltale (21 pins), TIDA01628_Power (53 pins), TIDA01628_Signal (41 pins), TIDA01628_Hardware (5 pins)
P1.2_STA: TIDA01628_Power (U1.2), TIDA01628_Signal (J5.11)
P1.3_RCK: TIDA01628_Telltale (TP16.1 U5.16 U6.16 U7.16), TIDA01628_Signal (J5.9)
P1.4_CLR: TIDA01628_Telltale (TP19.1 U5.13 U6.13 U7.13), TIDA01628_Signal (J5.7)
P2.4_G2: TIDA01628_Telltale (TP23.1 U5.3 U6.3 U7.3), TIDA01628_Signal (J5.3)
P2.5_G1: TIDA01628_Telltale (TP22.1 U5.2 U6.2 U7.2), TIDA01628_Signal (J5.1)
P2.7_SRCK: TIDA01628_Telltale (TP18.1 U5.17 U6.17 U7.17), TIDA01628_Signal (J4.15)
P3.2_EN: TIDA01628_Telltale (TP15.1 U5.14 U6.14 U7.14), TIDA01628_Signal (J4.13)
P3.3_SER_IN: TIDA01628_Telltale (TP17.1 U5.12), TIDA01628_Signal (J4.7)
P3.4: TIDA01628_Telltale (TP20.1 U7.15), TIDA01628_Signal (J4.5)
P3.7_ERR: TIDA01628_Telltale (TP21.1 U5.27 U6.27 U7.27), TIDA01628_Signal (J5.17)

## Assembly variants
001: not fitted C1 C54 FID1 FID2 FID3 R1 R64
